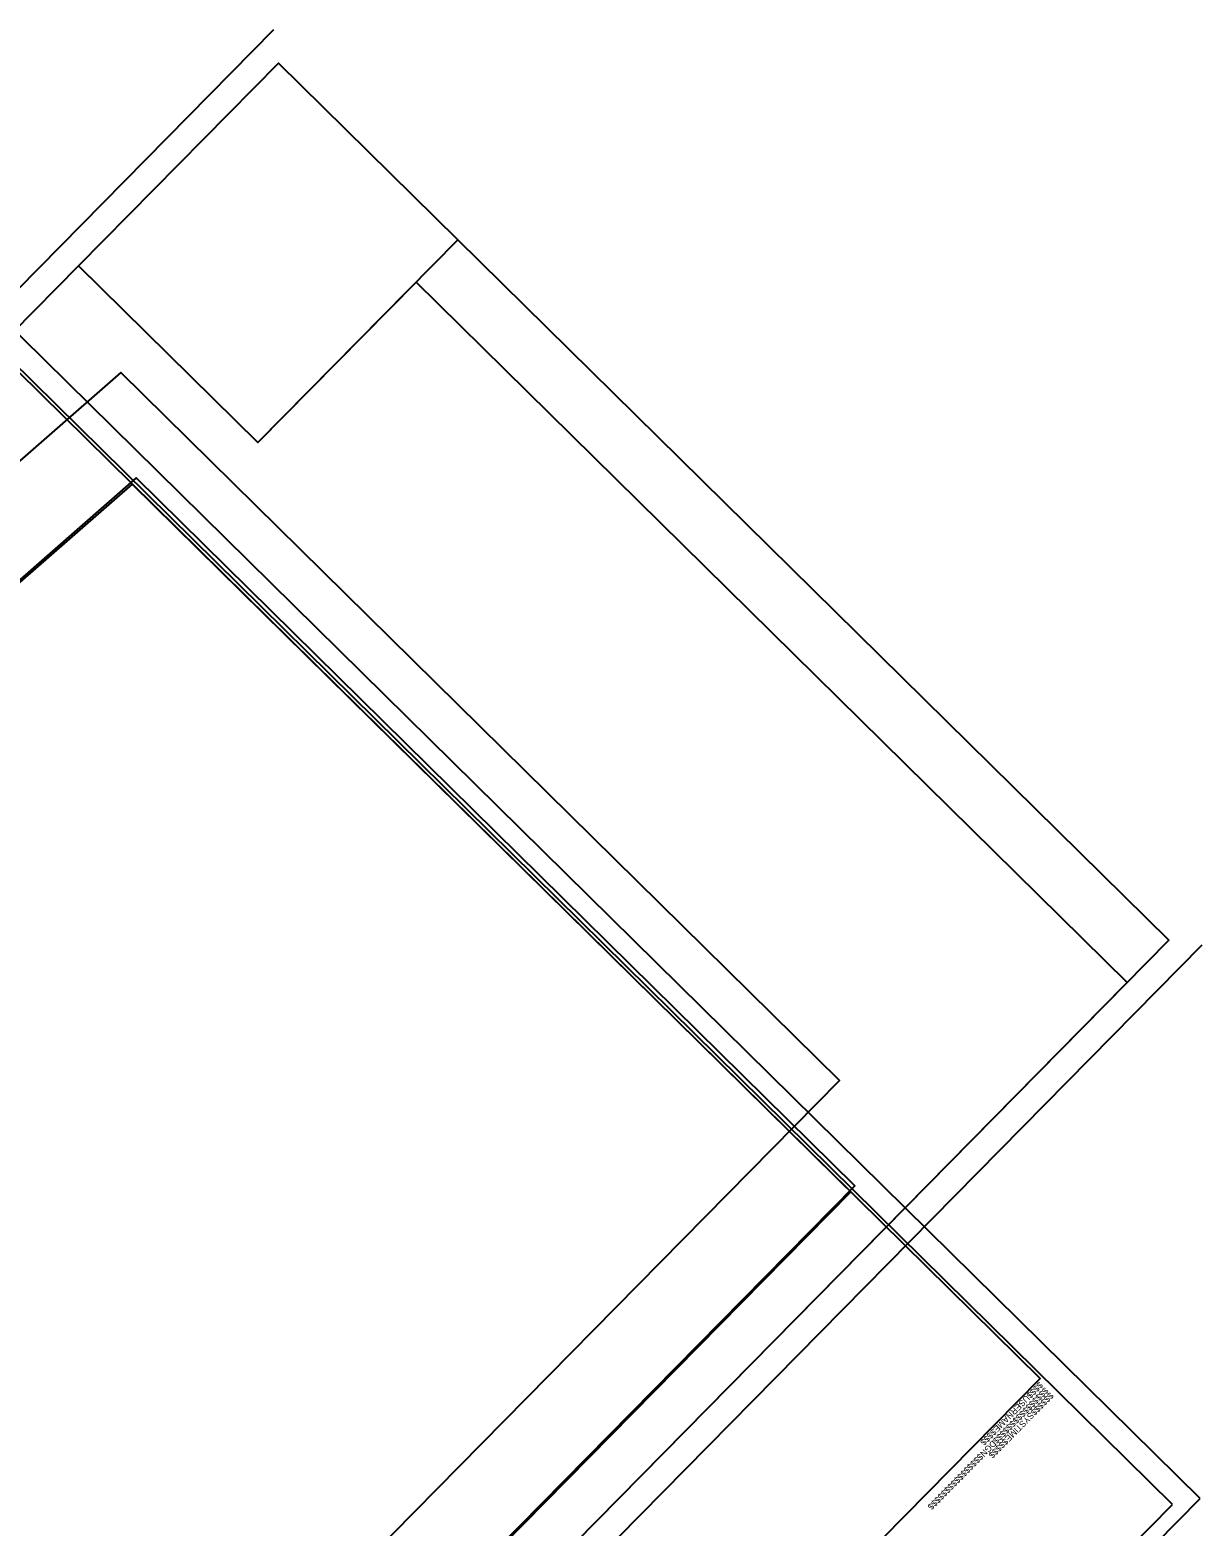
# Model space of a CAD drawing. Extents: x 1265903 to 1267873, y 771347 to 773361.
# Drawn here: x 1266888 to 1267873, y 772104 to 773361 of the extents above; entities that cross this region are included whole.
import ezdxf

# ---------------------------------------------------------------- set-up
doc = ezdxf.new("R2010")
doc.units = 0
for name, color, linetype in [('Exist Utilities Power Pole Cogo Elevation', 7, 'Continuous'), ('Exist Utilities Power UG Cable SUE LOS B Cogo Number', 7, 'Continuous'), ('Prop Conc 1ft 6in Curb and Gutter', 7, 'Continuous'), ('Prop Conc 4in Sidewalk', 7, 'Continuous'), ('Prop EOT', 7, 'Continuous'), ('Prop Horizontal Alignment Station Label', 7, 'Continuous'), ('Prop Plan Preparation Crest', 7, 'Continuous'), ('Prop Plan Preparation Watershed Post Construction', 7, 'Continuous'), ('Typical Terminator CELL', 7, 'Continuous')]:
    doc.layers.add(name, color=color, linetype=linetype)

msp = doc.modelspace()

# ---------------------------------------------------------------- linework, layer by layer
at = {"layer": 'Exist Utilities Power Pole Cogo Elevation'}
for points in [[(1266816.9, 771716), (1267567.9, 772478.1), (1266964.3, 773072.9), (1266841.4, 772965.6), (1266723.8, 773082.3), (1266663.9, 773007.3), (1266766.4, 772900.3), (1266377.8, 772561.3), (1266290.4, 772234.7)], [(1266829.9, 771627.4), (1267580.9, 772389.5), (1266977.3, 772984.3), (1266854.4, 772877), (1266736.9, 772993.7), (1266677, 772918.7), (1266779.5, 772811.7), (1266390.9, 772472.7), (1266303.5, 772146.1)], [(1266826.5, 771622.2), (1267577.5, 772384.4), (1266973.9, 772979.1), (1266851, 772871.9), (1266733.5, 772988.5), (1266673.6, 772913.6), (1266776.1, 772806.5), (1266387.5, 772467.5), (1266300.1, 772140.9)], [(1266826.5, 771622.2), (1267577.5, 772384.4), (1266973.9, 772979.1), (1266851, 772871.9), (1266733.5, 772988.5), (1266673.6, 772913.6), (1266776.1, 772806.5), (1266387.5, 772467.5), (1266300.1, 772140.9)]]:
    msp.add_lwpolyline(points, close=True, dxfattribs=at)
at = {"layer": 'Exist Utilities Power UG Cable SUE LOS B Cogo Number'}
msp.add_lwpolyline([(1266840.6, 771636.4), (1267577.5, 772384.4), (1266973.9, 772979.1), (1266387.5, 772467.5), (1266306, 772163.1)], close=True, dxfattribs=at)
at = {"layer": 'Prop Conc 1ft 6in Curb and Gutter'}
msp.add_lwpolyline([(1265931.1, 772532.5), (1266999.6, 771479.7), (1267736.6, 772227.6), (1266668.1, 773280.4)], close=True, dxfattribs=at)
at = {"layer": 'Prop Conc 4in Sidewalk'}
for p, q in [((1267092.6, 773360.6), (1265911.1, 772161.4)), ((1266691, 771392.9), (1267872.6, 772592.1))]:
    msp.add_line(p, q, dxfattribs=at)
at = {"layer": 'Prop EOT'}
msp.add_lwpolyline([(1267847.7, 772121.7), (1266661, 773291), (1265920.5, 772539.5), (1267107.2, 771370.2)], close=True, dxfattribs=at)
at = {"layer": 'Prop Horizontal Alignment Station Label'}
msp.add_lwpolyline([(1267871, 772126.8), (1266671.8, 773308.4), (1265903.3, 772528.4), (1267102.5, 771346.8)], close=True, dxfattribs=at)
at = {"layer": 'Prop Plan Preparation Crest'}
for points in [[(1267079.4, 773013.9), (1267247.4, 773184.3), (1267096.7, 773332.8), (1266928.8, 773162.3)], [(1266043.9, 772264.2), (1266791.9, 771527.3), (1267844.6, 772595.8), (1267247.4, 773184.3), (1267079.4, 773013.9), (1266928.8, 773162.3)]]:
    msp.add_lwpolyline(points, close=True, dxfattribs=at)
at = {"layer": 'Prop Plan Preparation Watershed Post Construction'}
msp.add_lwpolyline([(1266826.9, 771562.9), (1267809.6, 772560.2), (1267212.3, 773148.7), (1267079.4, 773013.9), (1266928.8, 773162.3), (1266079, 772299.9)], close=True, dxfattribs=at)
at = {"layer": 'Typical Terminator CELL'}
msp.add_lwpolyline([(1266826.9, 771562.9), (1267809.6, 772560.2), (1267212.3, 773148.7), (1267079.4, 773013.9), (1266928.8, 773162.3), (1266079, 772299.9)], close=True, dxfattribs=at)

# ---------------------------------------------------------------- texts
at = {"layer": 'Prop Conc 1ft 6in Curb and Gutter'}
for s, p in [('$$$$USERNAME$$$$', (1267735.7, 772225.2)), ('$$$$$$$$$$$$$$$$DGN$$$$$$$$$$$$$$$$', (1267740.4, 772220.6)), ('$$$$$$SYSTIME$$$$$', (1267744.7, 772216.4))]:
    msp.add_text(s, height=5.25, rotation=225.4239, dxfattribs=at).set_placement(p)

doc.saveas('drawing.dxf')
